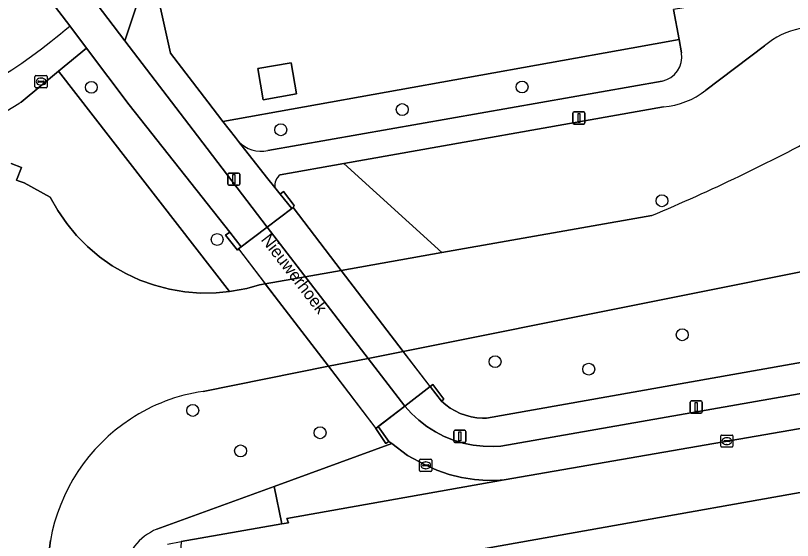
# Model space of a CAD drawing. Extents: x 157793 to 159380, y 380877 to 382313.
# Drawn here: x 158511.1 to 158574.9, y 381330.7 to 381373.8 of the extents above; entities that cross this region are included whole.
import ezdxf

# ---------------------------------------------------------------- set-up
doc = ezdxf.new("R2010")
doc.units = 0
for name, color, linetype in [('IMGEO_Boom', 7, 'Continuous'), ('IMGEO_Damwand', 7, 'Continuous'), ('IMGEO_Dek', 7, 'Continuous'), ('IMGEO_Erf', 7, 'Continuous'), ('IMGEO_Fietspad_gesloten', 7, 'Continuous'), ('IMGEO_Fietspad_open', 7, 'Continuous'), ('IMGEO_Groenvoorziening', 7, 'Continuous'), ('IMGEO_Hek', 7, 'Continuous'), ('IMGEO_Kolk', 7, 'Continuous'), ('IMGEO_Lichtmast', 7, 'Continuous'), ('IMGEO_Muur', 7, 'Continuous'), ('IMGEO_Openbare_ruimte_label', 7, 'Continuous'), ('IMGEO_Pand', 7, 'Continuous'), ('IMGEO_Rioolput', 7, 'Continuous'), ('IMGEO_Voetpad_gesloten', 7, 'Continuous'), ('IMGEO_Voetpad_halfverhard', 7, 'Continuous'), ('IMGEO_Voetpad_open', 7, 'Continuous'), ('IMGEO_Walbescherming', 7, 'Continuous'), ('IMGEO_Waterloop', 7, 'Continuous')]:
    doc.layers.add(name, color=color, linetype=linetype)

msp = doc.modelspace()

# ---------------------------------------------------------------- linework, layer by layer
at = {"layer": 'IMGEO_Boom'}
for centre in [(158552.722, 381367.944), (158517.344, 381367.917), (158542.883, 381366.085), (158532.904, 381364.428), (158564.214, 381358.593), (158527.678, 381355.406), (158565.88, 381347.573), (158550.505, 381345.362), (158558.197, 381344.747), (158525.672, 381341.354), (158536.13, 381339.52), (158529.604, 381338.025)]:
    msp.add_circle(centre, 0.489, dxfattribs=at)
at = {"layer": 'IMGEO_Damwand'}
for points in [[(158526.528, 381342.917), (158536.824, 381344.98), (158540.071, 381345.63), (158542.958, 381346.209)], [(158513.231, 381324.65), (158513.985, 381330.664)]]:
    msp.add_lwpolyline(points, dxfattribs=at)
for centre, radius, start, end in [((158528.598, 381328.504), 14.561, 98.17232, 123.51504), ((158528.785, 381328.071), 15.026, 123.19905, 170.06177)]:
    msp.add_arc(centre, radius, start, end, dxfattribs=at)
at = {"layer": 'IMGEO_Dek'}
msp.add_lwpolyline([(158537.868, 381352.868), (158533.911, 381358.046), (158533.805, 381357.965), (158531.789, 381356.428), (158529.652, 381354.799), (158529.435, 381354.633), (158531.627, 381351.764), (158536.824, 381344.98), (158540.713, 381339.878), (158540.897, 381340.035), (158543.081, 381341.707), (158545.174, 381343.309), (158542.958, 381346.209)], close=True, dxfattribs=at)
at = {"layer": 'IMGEO_Erf'}
for points in [[(158522.955, 381374.659), (158523.836, 381370.711), (158526.916, 381366.72), (158528.155, 381365.115), (158561.685, 381371.141), (158565.622, 381371.849), (158565.159, 381374.322)], [(158576.048, 381339.96), (158551.252, 381335.649)], [(158551.252, 381335.649), (158533.395, 381332.464), (158533.525, 381332.104), (158532.995, 381332.044), (158524.716, 381330.587), (158523.034, 381301.067), (158521.619, 381270.311), (158521.832, 381270.318)]]:
    msp.add_lwpolyline(points, dxfattribs=at)
for points in [[(158533.755, 381369.94), (158534.2, 381367.368), (158531.456, 381366.893), (158531.011, 381369.465)], [(158572.422, 381289.836), (158538.666, 381283.726), (158530.895, 381326.659), (158580.795, 381335.543), (158582.739, 381324.624), (158574.342, 381323.085), (158545.629, 381317.824), (158549.522, 381296.751), (158570.477, 381300.622)]]:
    msp.add_lwpolyline(points, close=True, dxfattribs=at)
at = {"layer": 'IMGEO_Fietspad_gesloten'}
msp.add_lwpolyline([(158531.789, 381356.428), (158529.435, 381354.633), (158540.713, 381339.878), (158543.081, 381341.707)], close=True, dxfattribs=at)
at = {"layer": 'IMGEO_Fietspad_open'}
msp.add_lwpolyline([(158520.463, 381366.488), (158528.71, 381356.012), (158529.652, 381354.799), (158531.789, 381356.428), (158526.059, 381363.92), (158520.104, 381371.739), (158513.621, 381380.251), (158511.348, 381378.54), (158512.514, 381376.986), (158515.564, 381372.958), (158516.943, 381371.137)], close=True, dxfattribs=at)
msp.add_lwpolyline([(158576.125, 381342.819), (158550.99, 381338.428), (158550.343, 381338.393), (158549.518, 381338.414), (158548.698, 381338.509), (158547.89, 381338.677), (158547.1, 381338.916), (158546.334, 381339.225), (158545.6, 381339.601), (158544.901, 381340.041), (158544.245, 381340.541), (158543.637, 381341.099), (158543.081, 381341.707), (158540.897, 381340.035), (158541.769, 381338.809), (158542.021, 381338.636), (158543.31, 381337.639), (158544.75, 381336.872), (158545.719, 381336.435), (158546.723, 381336.087), (158547.754, 381335.83), (158548.804, 381335.666), (158549.865, 381335.597), (158550.927, 381335.622), (158551.252, 381335.649), (158576.048, 381339.96)], dxfattribs=at)
at = {"layer": 'IMGEO_Groenvoorziening'}
for points in [[(158512.75, 381381.808), (158512.985, 381381.086), (158513.621, 381380.251), (158520.104, 381371.739), (158522.607, 381379.358)], [(158515.564, 381372.958), (158512.514, 381376.986)], [(158565.829, 381370.742), (158565.622, 381371.849), (158561.685, 381371.141), (158528.155, 381365.115), (158529.177, 381363.791), (158529.433, 381363.464)], [(158532.425, 381359.674), (158532.86, 381359.135), (158533.12, 381359.365), (158534.001, 381358.196), (158533.911, 381358.046), (158533.805, 381357.965), (158531.789, 381356.428), (158529.652, 381354.799), (158529.435, 381354.633), (158529.335, 381354.543), (158528.364, 381355.762), (158528.71, 381356.012), (158520.463, 381366.488), (158516.943, 381371.137), (158514.649, 381369.24), (158528.701, 381351.132), (158528.862, 381351.148), (158530.119, 381351.391), (158531.144, 381351.678), (158531.627, 381351.764), (158534.919, 381352.346), (158537.868, 381352.868), (158546.133, 381354.331), (158538.07, 381361.65)], [(158572.638, 381371.329), (158567.812, 381367.674)], [(158510.755, 381361.663), (158511.599, 381361.326), (158511.2, 381360.296), (158511.346, 381360.23), (158511.813, 381360.067), (158513.974, 381358.896), (158514.599, 381357.778), (158515.32, 381356.721), (158516.134, 381355.732), (158517.032, 381354.82), (158518.009, 381353.991), (158519.055, 381353.254), (158520.164, 381352.612), (158521.325, 381352.072), (158522.529, 381351.639), (158523.768, 381351.314), (158525.031, 381351.102), (158526.307, 381351.003), (158527.588, 381351.018), (158528.701, 381351.132), (158514.649, 381369.24)], [(158514.649, 381369.24), (158511.569, 381366.691), (158511.392, 381366.579)], [(158531.827, 381362.714), (158564.221, 381368.432)], [(158564.343, 381366.312), (158538.07, 381361.65), (158546.133, 381354.331), (158563.379, 381357.383)], [(158538.07, 381361.65), (158532.859, 381360.725)], [(158581.085, 381353.848), (158542.958, 381346.209), (158540.071, 381345.63), (158536.824, 381344.98), (158526.528, 381342.917)], [(158522.731, 381331.594), (158532.363, 381335.112), (158542.021, 381338.636), (158541.769, 381338.809), (158541.539, 381338.649), (158540.713, 381339.878), (158540.897, 381340.035), (158543.081, 381341.707), (158545.174, 381343.309), (158545.395, 381343.481), (158546.286, 381342.292), (158546.096, 381342.112), (158546.45, 381341.81), (158546.829, 381341.541), (158547.23, 381341.308), (158547.651, 381341.11), (158548.088, 381340.952), (158548.538, 381340.833), (158548.996, 381340.754), (158549.459, 381340.717), (158549.798, 381340.716), (158576.523, 381345.449)], [(158513.985, 381330.664), (158513.231, 381324.65)]]:
    msp.add_lwpolyline(points, dxfattribs=at)
for centre, radius, start, end in [((158485.443, 381407.867), 46.108, 291.00713, 310.78887), ((158576.97, 381366.133), 6.765, 101.97136, 129.82085), ((158563.819, 381370.426), 2.034, 281.38399, 8.93216), ((158563.782, 381372.84), 6.552, 274.91271, 307.95926), ((158497.785, 381388.283), 25.617, 281.71701, 302.08547), ((158504.672, 381497.575), 151.988, 292.72218, 298.66912), ((158531.286, 381365.182), 2.527, 222.83808, 282.37212), ((158533.514, 381359.839), 1.102, 126.49341, 188.63121), ((158528.598, 381328.504), 14.561, 98.17232, 123.51504), ((158528.785, 381328.071), 15.026, 123.19905, 170.06177), ((158524.484, 381327.395), 4.55, 112.66164, 171.48045)]:
    msp.add_arc(centre, radius, start, end, dxfattribs=at)
at = {"layer": 'IMGEO_Hek'}
for points in [[(158533.911, 381358.046), (158537.868, 381352.868)], [(158529.435, 381354.633), (158531.627, 381351.764)], [(158537.868, 381352.868), (158542.958, 381346.209)], [(158536.824, 381344.98), (158531.627, 381351.764)], [(158545.174, 381343.309), (158542.958, 381346.209)], [(158536.824, 381344.98), (158540.713, 381339.878)]]:
    msp.add_lwpolyline(points, dxfattribs=at)
at = {"layer": 'IMGEO_Kolk'}
for p, q in [((158569.041, 381338.404), (158569.041, 381339.256)), ((158569.116, 381339.33), (158569.968, 381339.33)), ((158569.529, 381339.11), (158569.554, 381339.11)), ((158570.042, 381339.256), (158570.042, 381338.404)), ((158569.3, 381338.824), (158569.3, 381338.836)), ((158569.738, 381338.787), (158569.34, 381338.787)), ((158569.343, 381338.873), (158569.741, 381338.873)), ((158569.552, 381338.55), (158569.527, 381338.55)), ((158569.784, 381338.836), (158569.784, 381338.824)), ((158569.968, 381338.33), (158569.116, 381338.33)), ((158544.31, 381336.416), (158544.31, 381337.268)), ((158544.385, 381337.342), (158545.237, 381337.342)), ((158545.311, 381337.268), (158545.311, 381336.416)), ((158544.569, 381336.836), (158544.569, 381336.848)), ((158545.007, 381336.799), (158544.609, 381336.799)), ((158544.612, 381336.885), (158545.01, 381336.885)), ((158544.821, 381336.562), (158544.796, 381336.562)), ((158544.798, 381337.122), (158544.823, 381337.122)), ((158545.053, 381336.848), (158545.053, 381336.836)), ((158545.237, 381336.342), (158544.385, 381336.342))]:
    msp.add_line(p, q, dxfattribs=at)
for points in [[(158569.041, 381338.404), (158569.041, 381339.256)], [(158569.116, 381339.33), (158569.968, 381339.33)], [(158570.042, 381339.256), (158570.042, 381338.404)], [(158569.968, 381338.33), (158569.116, 381338.33)], [(158544.31, 381336.416), (158544.31, 381337.268)], [(158544.385, 381337.342), (158545.237, 381337.342)], [(158545.311, 381337.268), (158545.311, 381336.416)], [(158545.237, 381336.342), (158544.385, 381336.342)]]:
    msp.add_lwpolyline(points, dxfattribs=at)
for centre, radius, start, end in [((158569.118, 381339.254), 0.0765, 91.55205, 178.44795), ((158569.118, 381339.254), 0.0765, 91.55205, 178.44795), ((158569.966, 381339.254), 0.0765, 1.55205, 88.44795), ((158569.966, 381339.254), 0.0765, 1.55205, 88.44795), ((158569.34, 381338.833), 0.0403, 85.87752, 175.75265), ((158569.337, 381338.823), 0.0366, 178.93798, 274.71019), ((158569.741, 381338.83), 0.043, 264.86636, 352.45326), ((158569.745, 381338.835), 0.0386, 1.73085, 96.63898), ((158569.118, 381338.406), 0.0765, 181.55205, 268.44795), ((158569.118, 381338.406), 0.0765, 181.55205, 268.44795), ((158569.966, 381338.406), 0.0765, 271.55205, 358.44795), ((158569.966, 381338.406), 0.0765, 271.55205, 358.44795), ((158544.387, 381337.266), 0.0765, 91.55205, 178.44795), ((158544.387, 381337.266), 0.0765, 91.55205, 178.44795), ((158545.235, 381337.266), 0.0765, 1.55205, 88.44795), ((158545.235, 381337.266), 0.0765, 1.55205, 88.44795), ((158544.609, 381336.845), 0.0403, 85.87752, 175.75265), ((158544.606, 381336.835), 0.0366, 178.93798, 274.71019), ((158545.01, 381336.842), 0.043, 264.86636, 352.45326), ((158545.014, 381336.847), 0.0386, 1.73085, 96.63898), ((158544.387, 381336.418), 0.0765, 181.55205, 268.44795), ((158544.387, 381336.418), 0.0765, 181.55205, 268.44795), ((158545.235, 381336.418), 0.0765, 271.55205, 358.44795), ((158545.235, 381336.418), 0.0765, 271.55205, 358.44795)]:
    msp.add_arc(centre, radius, start, end, dxfattribs=at)
for centre, major_axis, ratio, start_param, end_param in [((158569.528, 381338.83), (-0.387, 0.002), 0.722429, 4.712389, 7.853982), ((158569.553, 381338.83), (-0.39, 0.002), 0.717154, 1.570796, 4.712389), ((158544.797, 381336.842), (-0.387, 0.002), 0.722429, 4.712389, 7.853982), ((158544.822, 381336.842), (-0.39, 0.002), 0.717154, 1.570796, 4.712389)]:
    msp.add_ellipse(centre, major_axis=major_axis, ratio=ratio, start_param=start_param, end_param=end_param, dxfattribs=at)
at = {"layer": 'IMGEO_Lichtmast'}
for p, q in [((158556.998, 381365.89), (158557.788, 381365.89)), ((158557.788, 381365.89), (158556.998, 381365.89)), ((158556.898, 381364.99), (158556.898, 381365.79)), ((158556.898, 381365.79), (158556.898, 381364.99)), ((158557.888, 381365.79), (158557.888, 381364.99)), ((158557.888, 381364.99), (158557.888, 381365.79)), ((158557.788, 381364.89), (158556.998, 381364.89)), ((158556.998, 381364.89), (158557.788, 381364.89)), ((158528.548, 381359.968), (158528.548, 381360.768)), ((158528.548, 381360.768), (158528.548, 381359.968)), ((158528.648, 381360.868), (158529.438, 381360.868)), ((158529.438, 381360.868), (158528.648, 381360.868)), ((158529.538, 381360.768), (158529.538, 381359.968)), ((158529.538, 381359.968), (158529.538, 381360.768)), ((158529.438, 381359.868), (158528.648, 381359.868)), ((158528.648, 381359.868), (158529.438, 381359.868)), ((158566.524, 381341.231), (158566.524, 381342.031)), ((158566.524, 381342.031), (158566.524, 381341.231)), ((158566.624, 381342.131), (158567.414, 381342.131)), ((158567.414, 381342.131), (158566.624, 381342.131)), ((158567.514, 381342.031), (158567.514, 381341.231)), ((158567.514, 381341.231), (158567.514, 381342.031)), ((158567.414, 381341.131), (158566.624, 381341.131)), ((158566.624, 381341.131), (158567.414, 381341.131)), ((158547.213, 381339.719), (158548.003, 381339.719)), ((158548.003, 381339.719), (158547.213, 381339.719)), ((158547.113, 381338.819), (158547.113, 381339.619)), ((158547.113, 381339.619), (158547.113, 381338.819)), ((158548.103, 381339.619), (158548.103, 381338.819)), ((158548.103, 381338.819), (158548.103, 381339.619)), ((158548.003, 381338.719), (158547.213, 381338.719)), ((158547.213, 381338.719), (158548.003, 381338.719))]:
    msp.add_line(p, q, dxfattribs=at)
for points in [[(158557.318, 381365.765), (158557.468, 381365.765), (158557.468, 381365.015), (158557.318, 381365.015), (158557.318, 381365.765)], [(158528.968, 381360.743), (158529.118, 381360.743), (158529.118, 381359.993), (158528.968, 381359.993), (158528.968, 381360.743)], [(158566.944, 381342.006), (158567.094, 381342.006), (158567.094, 381341.256), (158566.944, 381341.256), (158566.944, 381342.006)], [(158547.533, 381339.594), (158547.683, 381339.594), (158547.683, 381338.844), (158547.533, 381338.844), (158547.533, 381339.594)]]:
    msp.add_lwpolyline(points, dxfattribs=at)
for centre, start, end in [((158556.998, 381365.79), 90, 180), ((158556.998, 381365.79), 90, 180), ((158557.788, 381365.79), 0, 90), ((158557.788, 381365.79), 360, 90), ((158556.998, 381364.99), 180, 270), ((158556.998, 381364.99), 180, 270), ((158557.788, 381364.99), 270, 0), ((158557.788, 381364.99), 270, 0), ((158528.648, 381360.768), 90, 180), ((158528.648, 381360.768), 90, 180), ((158529.438, 381360.768), 0, 90), ((158529.438, 381360.768), 360, 90), ((158528.648, 381359.968), 180, 270), ((158528.648, 381359.968), 180, 270), ((158529.438, 381359.968), 270, 0), ((158529.438, 381359.968), 270, 0), ((158566.624, 381342.031), 90, 180), ((158566.624, 381342.031), 90, 180), ((158567.414, 381342.031), 0, 90), ((158567.414, 381342.031), 360, 90), ((158566.624, 381341.231), 180, 270), ((158566.624, 381341.231), 180, 270), ((158567.414, 381341.231), 270, 0), ((158567.414, 381341.231), 270, 0), ((158547.213, 381339.619), 90, 180), ((158547.213, 381339.619), 90, 180), ((158548.003, 381339.619), 0, 90), ((158548.003, 381339.619), 360, 90), ((158547.213, 381338.819), 180, 270), ((158547.213, 381338.819), 180, 270), ((158548.003, 381338.819), 270, 0), ((158548.003, 381338.819), 270, 0)]:
    msp.add_arc(centre, 0.1, start, end, dxfattribs=at)
at = {"layer": 'IMGEO_Muur'}
for points in [[(158534.001, 381358.196), (158533.12, 381359.365), (158532.86, 381359.135), (158533.805, 381357.965), (158533.911, 381358.046)], [(158528.71, 381356.012), (158528.364, 381355.762), (158529.335, 381354.543), (158529.435, 381354.633), (158529.652, 381354.799)], [(158546.286, 381342.292), (158545.395, 381343.481), (158545.174, 381343.309), (158546.096, 381342.112)], [(158541.539, 381338.649), (158541.769, 381338.809), (158540.897, 381340.035), (158540.713, 381339.878)]]:
    msp.add_lwpolyline(points, close=True, dxfattribs=at)
at = {"layer": 'IMGEO_Pand'}
for points in [[(158533.755, 381369.94), (158531.011, 381369.465), (158531.456, 381366.893), (158534.2, 381367.368)], [(158570.477, 381300.622), (158549.522, 381296.751), (158545.629, 381317.824), (158574.342, 381323.085), (158582.739, 381324.624), (158580.795, 381335.543), (158530.895, 381326.659), (158538.666, 381283.726), (158572.422, 381289.836)]]:
    msp.add_lwpolyline(points, close=True, dxfattribs=at)
at = {"layer": 'IMGEO_Rioolput'}
for p, q in [((158512.715, 381367.96), (158512.715, 381368.812)), ((158512.79, 381368.886), (158513.642, 381368.886)), ((158513.017, 381368.429), (158513.415, 381368.429)), ((158513.203, 381368.666), (158513.228, 381368.666)), ((158513.716, 381368.812), (158513.716, 381367.96)), ((158513.642, 381367.886), (158512.79, 381367.886)), ((158512.974, 381368.38), (158512.974, 381368.392)), ((158513.412, 381368.343), (158513.014, 381368.343)), ((158513.226, 381368.106), (158513.201, 381368.106)), ((158513.458, 381368.392), (158513.458, 381368.38))]:
    msp.add_line(p, q, dxfattribs=at)
for points in [[(158512.715, 381367.96), (158512.715, 381368.812)], [(158512.79, 381368.886), (158513.642, 381368.886)], [(158513.716, 381368.812), (158513.716, 381367.96)], [(158513.642, 381367.886), (158512.79, 381367.886)]]:
    msp.add_lwpolyline(points, dxfattribs=at)
for centre, radius, start, end in [((158512.792, 381368.81), 0.0765, 91.55205, 178.44795), ((158512.792, 381368.81), 0.0765, 91.55205, 178.44795), ((158513.014, 381368.389), 0.0403, 85.87752, 175.75265), ((158513.419, 381368.391), 0.0386, 1.73085, 96.63898), ((158513.64, 381368.81), 0.0765, 1.55205, 88.44795), ((158513.64, 381368.81), 0.0765, 1.55205, 88.44795), ((158512.792, 381367.962), 0.0765, 181.55205, 268.44795), ((158512.792, 381367.962), 0.0765, 181.55205, 268.44795), ((158513.011, 381368.379), 0.0366, 178.93798, 274.71019), ((158513.415, 381368.386), 0.043, 264.86636, 352.45326), ((158513.64, 381367.962), 0.0765, 271.55205, 358.44795), ((158513.64, 381367.962), 0.0765, 271.55205, 358.44795)]:
    msp.add_arc(centre, radius, start, end, dxfattribs=at)
for centre, major_axis, ratio, start_param, end_param in [((158513.202, 381368.386), (-0.387, 0.002), 0.722429, 4.712389, 7.853982), ((158513.227, 381368.386), (-0.39, 0.002), 0.717154, 1.570796, 4.712389)]:
    msp.add_ellipse(centre, major_axis=major_axis, ratio=ratio, start_param=start_param, end_param=end_param, dxfattribs=at)
at = {"layer": 'IMGEO_Voetpad_gesloten'}
msp.add_lwpolyline([(158533.911, 381358.046), (158531.789, 381356.428), (158543.081, 381341.707), (158545.174, 381343.309)], close=True, dxfattribs=at)
at = {"layer": 'IMGEO_Voetpad_halfverhard'}
for points in [[(158514.649, 381369.24), (158516.943, 381371.137), (158515.564, 381372.958)], [(158511.392, 381366.579), (158511.569, 381366.691), (158514.649, 381369.24)], [(158523.604, 381330.348), (158524.716, 381330.587), (158532.995, 381332.044), (158532.363, 381335.112), (158522.731, 381331.594)]]:
    msp.add_lwpolyline(points, dxfattribs=at)
for centre, radius, start, end in [((158485.443, 381407.867), 46.108, 291.00713, 310.78887), ((158497.785, 381388.283), 25.617, 281.71701, 302.08547), ((158524.484, 381327.395), 4.55, 112.66164, 171.48045)]:
    msp.add_arc(centre, radius, start, end, dxfattribs=at)
at = {"layer": 'IMGEO_Voetpad_open'}
for points in [[(158522.955, 381374.659), (158524.606, 381379.739), (158523.436, 381386.339), (158524.951, 381386.653), (158524.79, 381387.653), (158524.554, 381388.922), (158522.631, 381388.518), (158521.991, 381391.998), (158519.46, 381391.531), (158520.755, 381384.339), (158521.672, 381384.506), (158522.607, 381379.358), (158520.104, 381371.739), (158526.059, 381363.92), (158531.789, 381356.428), (158533.805, 381357.965), (158532.86, 381359.135), (158532.425, 381359.674), (158531.737, 381360.526), (158529.433, 381363.464), (158529.177, 381363.791), (158528.155, 381365.115), (158526.916, 381366.72), (158523.836, 381370.711)], [(158532.363, 381335.112), (158532.995, 381332.044), (158533.525, 381332.104), (158533.395, 381332.464), (158551.252, 381335.649), (158550.927, 381335.622), (158549.865, 381335.597), (158548.804, 381335.666), (158547.754, 381335.83), (158546.723, 381336.087), (158545.719, 381336.435), (158544.75, 381336.872), (158543.31, 381337.639), (158542.021, 381338.636)]]:
    msp.add_lwpolyline(points, close=True, dxfattribs=at)
for points in [[(158568.049, 381374.772), (158565.159, 381374.322), (158565.622, 381371.849), (158565.829, 381370.742)], [(158567.812, 381367.674), (158572.638, 381371.329)], [(158564.221, 381368.432), (158531.827, 381362.714)], [(158532.859, 381360.725), (158538.07, 381361.65), (158564.343, 381366.312)], [(158529.433, 381363.464), (158531.737, 381360.526), (158532.425, 381359.674)], [(158576.523, 381345.449), (158549.798, 381340.716), (158549.459, 381340.717), (158548.996, 381340.754), (158548.538, 381340.833), (158548.088, 381340.952), (158547.651, 381341.11), (158547.23, 381341.308), (158546.829, 381341.541), (158546.45, 381341.81), (158546.096, 381342.112), (158545.174, 381343.309), (158543.081, 381341.707), (158543.637, 381341.099), (158544.245, 381340.541), (158544.901, 381340.041), (158545.6, 381339.601), (158546.334, 381339.225), (158547.1, 381338.916), (158547.89, 381338.677), (158548.698, 381338.509), (158549.518, 381338.414), (158550.343, 381338.393), (158550.99, 381338.428), (158576.125, 381342.819)]]:
    msp.add_lwpolyline(points, dxfattribs=at)
for centre, radius, start, end in [((158576.97, 381366.133), 6.765, 101.97136, 129.82085), ((158563.819, 381370.426), 2.034, 281.38399, 8.93216), ((158563.782, 381372.84), 6.552, 274.91271, 307.95926), ((158531.286, 381365.182), 2.527, 222.83808, 282.37212), ((158533.514, 381359.839), 1.102, 126.49341, 188.63121)]:
    msp.add_arc(centre, radius, start, end, dxfattribs=at)
at = {"layer": 'IMGEO_Walbescherming'}
msp.add_lwpolyline([(158534.919, 381352.346), (158531.627, 381351.764)], dxfattribs=at)
at = {"layer": 'IMGEO_Waterloop'}
for points in [[(158563.379, 381357.383), (158546.133, 381354.331), (158537.868, 381352.868), (158534.919, 381352.346), (158531.627, 381351.764), (158531.144, 381351.678), (158530.119, 381351.391), (158528.862, 381351.148), (158528.701, 381351.132), (158527.588, 381351.018), (158526.307, 381351.003), (158525.031, 381351.102), (158523.768, 381351.314), (158522.529, 381351.639), (158521.325, 381352.072), (158520.164, 381352.612), (158519.055, 381353.254), (158518.009, 381353.991), (158517.032, 381354.82), (158516.134, 381355.732), (158515.32, 381356.721), (158514.599, 381357.778), (158513.974, 381358.896), (158511.813, 381360.067), (158511.346, 381360.23), (158511.2, 381360.296), (158511.599, 381361.326), (158510.755, 381361.663)], [(158526.528, 381342.917), (158536.824, 381344.98), (158540.071, 381345.63), (158542.958, 381346.209), (158581.085, 381353.848)], [(158513.231, 381324.65), (158513.985, 381330.664)]]:
    msp.add_lwpolyline(points, dxfattribs=at)
for centre, radius, start, end in [((158504.672, 381497.575), 151.988, 292.72218, 298.66912), ((158528.598, 381328.504), 14.561, 98.17232, 123.51504), ((158528.785, 381328.071), 15.026, 123.19905, 170.06177)]:
    msp.add_arc(centre, radius, start, end, dxfattribs=at)

# ---------------------------------------------------------------- texts
at = {"layer": 'IMGEO_Openbare_ruimte_label'}
msp.add_text('Nieuwerhoek', height=1, rotation=307.68393, dxfattribs=at).set_placement((158531.231, 381355.382))

doc.saveas('drawing.dxf')
